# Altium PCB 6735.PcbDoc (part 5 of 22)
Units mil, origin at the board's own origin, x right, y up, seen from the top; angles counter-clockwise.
Board outline 2641.73 x 5165.35 mil, 6 copper layers (Top, Inner Layer 2, Inner Layer 3, Inner Layer 4, Inner Layer 5, Bottom), stack 35.7 mil thick; 1011 components, 790 nets, 4118 pads, 9325 vias.
Unrouted connection lines stored in the file: 4610.
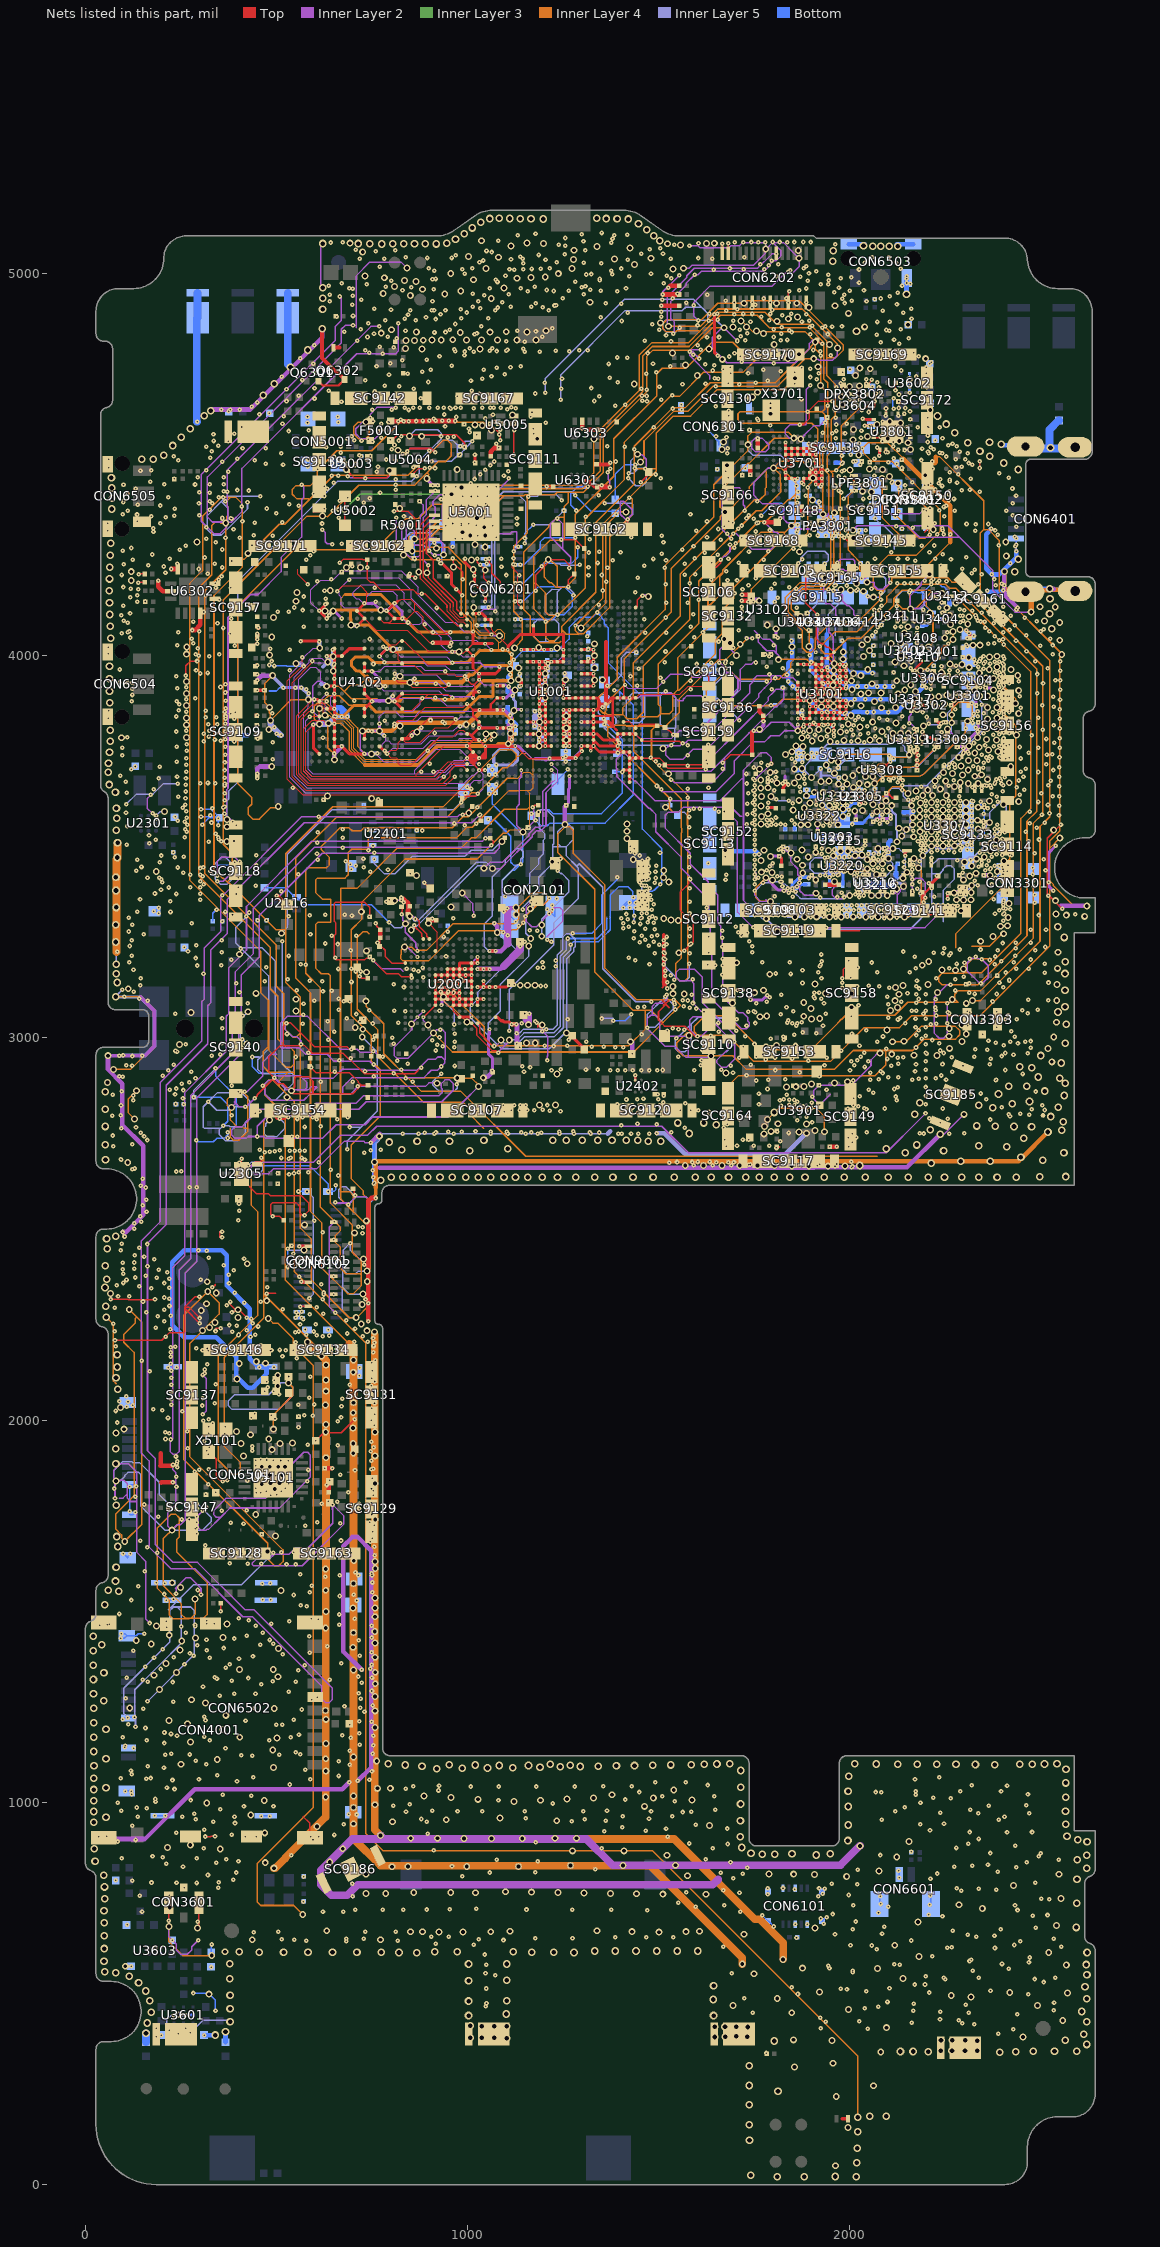
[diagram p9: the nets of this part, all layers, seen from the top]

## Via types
v1: diameter 12, hole 4, Top to Inner Layer 2, 3329 vias
v2: diameter 12, hole 4, Inner Layer 5 to Bottom, 3071 vias
v3: diameter 18, hole 10, Inner Layer 2 to Inner Layer 5, 1928 vias
v4: diameter 10, hole 4, Top to Inner Layer 2, 525 vias
v5: diameter 20, hole 12, Top to Bottom, 472 vias

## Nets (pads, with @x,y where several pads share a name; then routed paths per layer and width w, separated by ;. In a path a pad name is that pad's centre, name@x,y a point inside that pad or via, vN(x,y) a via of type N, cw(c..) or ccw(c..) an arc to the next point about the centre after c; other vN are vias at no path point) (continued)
CHD_DM: U1001.T4 U2001.M1 | length 749.7
  Top w4: v1(863.31,3311.09) 868.02,3311.09 872.95,3306.16 ; 872.95,3306.49 872.95,3306.16 ; U2001.M1@899.83,3258.94 892.94,3265.83 892.94,3272.17 872.95,3292.16 872.95,3306.16
  Inner Layer 2 w3: v4(1218.95,3716.51) 1235.45,3700.01 1235.45,3670.99 1228.95,3664.49
  Inner Layer 2 w4: v3(848.31,3318.09) 856.31,3318.09 v1(863.31,3311.09) ; v3(1064.99,3443.16) 1085.56,3443.16 1168.97,3526.56 1168.97,3530.96 1180.6,3542.59 1192.34,3542.59 1204.95,3555.21 1204.95,3642.03 1218.03,3655.11 1222.92,3660 1225.98,3663.05 1227.52,3663.05 1228.95,3664.49
  Inner Layer 5 w4: v3(848.31,3318.09) 859.31,3307.09 870.62,3307.09 1022.62,3459.09 1049.06,3459.09 v3(1064.99,3443.16)
CHD_DP: U1001.T3 U2001.N1 | length 697.7
  Top w4: v1(860.31,3295.09) 858.97,3293.74 880.31,3272.4 880.31,3265.21 885.34,3260.19 U2001.N1@884.09,3258.94
  Inner Layer 2 w3: v4(1218.95,3700.77) 1229.45,3690.26 1229.45,3675.99 1225.26,3671.8 1224.95,3671.8
  Inner Layer 2 w4: v3(852.41,3282.29) 851.19,3283.52 861.54,3293.87 v1(860.31,3295.09) ; v3(1042.86,3443.89) 1058.06,3459.09 1090.18,3459.09 1159.31,3528.22 1159.31,3532.62 1177.78,3551.09 1189.52,3551.09 1196.95,3558.52 1196.95,3645.35 1223.4,3671.8 1224.95,3671.8
  Inner Layer 5 w4: v3(852.41,3282.29) 857.16,3282.29 1024.95,3450.09 1042.86,3450.09 v3(1042.86,3443.89)
CHR_LDO: C2041.1 R2192.2 U2001.P3 U2116.1 | length 553.8
  Top w4: C2041.1@826.95,3343.49 828.31,3343.49 828.31,3337.49 v1(827.31,3323.09)
  Inner Layer 2 w4: v1(827.31,3323.09) 830.31,3323.09 830.31,3307.91 838.17,3300.05 v3(836.95,3298.83) 836.95,3276.54 864.45,3249.04 864.45,3238.53 868.34,3234.64 v4(868.34,3227.44)
  Inner Layer 5 w4: v2(794.22,3302.72) 808.85,3288.09 826.21,3288.09 v3(836.95,3298.83)
  Bottom w4: R2192.2@468.31,3393.09 523.14,3393.09 548.39,3367.83 U2116.1@551.93,3367.84 571.68,3348.09 748.85,3348.09 v2(794.22,3302.72)
CKE: U1001.D4 U4102.R2 U4102.T2 | length 665.2
  Top w3: v1(587.08,3840.61) 588,3841.52 U4102.T2@611.82,3841.53 U4102.R2@611.82,3861.21
  Inner Layer 2 w3: v1(587.08,3840.61) 576.58,3830.11 576.58,3700.36 592.33,3684.61 914.48,3684.61 924.46,3694.58 941.31,3694.58 966.46,3719.74 1026.75,3719.74 v4(1029.98,3716.51)
CLK0_C: U1001.E9 U4102.N3 | length 634.7
  Top w3: U1001.E9@1045.72,3795.25 v4(1045.73,3779.5)
  Inner Layer 2 w3: v3(612.08,3862.11) 620.08,3870.11 620.08,3889.16 v1(631.5,3900.58) ; v4(1045.73,3779.5) 1045.73,3792.75 v3(1048.08,3795.11)
  Inner Layer 4 w3: v3(612.08,3862.11) 628.22,3862.11 654.28,3836.05 678.01,3836.05 702.48,3811.58 702.48,3758.22 731.23,3729.47 865.08,3729.47 914.71,3779.11 1043.08,3779.11 1048.08,3784.11 v3(1048.08,3795.11)
CLK0_T: U1001.F9 U4102.P3 | length 622.5
  Top w3: v4(1061.47,3779.5) U1001.F9@1061.47,3795.25
  Inner Layer 2 w3: v3(627.08,3844.11) 627.08,3876.48 v1(631.5,3880.89) ; v4(1061.47,3779.5) 1061.47,3784.41 v3(1069.35,3792.29)
  Inner Layer 4 w3: v3(627.08,3844.11) 637.69,3844.11 651.77,3830.03 675.54,3830.03 696.48,3809.09 696.48,3755.64 728.7,3723.42 867.51,3723.42 917.2,3773.11 1046.08,3773.11 1057.84,3784.86 1061.93,3784.86 v3(1069.35,3792.29)
CLK_WCN: R5001.3 U3101.H1 | length 2463.2
  Top w4: R5001.3@849.08,4341.11 850.95,4341.11 v1(850.95,4335.49)
  Inner Layer 2 w4: v1(850.95,4335.49) 860.73,4325.71 v3(860.73,4305.07) ; v3(1893.37,4023.8) 1894.01,4024.44 1910.27,4008.19 v4(1910.9,4008.83)
  Inner Layer 4 w4: v3(860.73,4305.07) 886.37,4305.07 920.39,4339.09 1024.4,4339.09 1052.93,4367.63 1052.93,4405.09 1084.74,4436.9 1300.65,4436.9 1346.27,4482.52 1346.27,4579.66 1458.19,4691.57 1458.19,4784.27 1482.88,4808.97 1579.3,4808.97 1660.82,4890.49 1757.44,4890.49 1790.34,4857.59 1894.01,4857.59 1931.31,4820.29 1931.31,4724.87 1942.31,4713.87 1942.31,4543.8 1929.31,4530.8 1929.31,4489.62 1944.31,4474.62 1944.31,4361.92 1950.22,4356.01 1950.22,4197.9 1933.66,4181.33 1897.18,4181.33 1895.97,4182.55 1872.51,4182.55 1839.1,4149.15 1839.1,4120.46 1839.18,4120.38 1839.18,4113.63 1893.37,4059.43 v3(1893.37,4023.8)
CMMCLK: CON6201.20 R6212.2 U1001.Y27 | length 1079.4
  Top w3: v4(1281.94,4078.72) U1001.Y27@1281.94,4079.48 ; v4(1281.94,4078.72) U1001.Y27@1281.94,4079.48 ; v4(1281.94,4078.72) U1001.Y27@1281.94,4079.48 ; v4(1281.94,4078.72) U1001.Y27@1281.94,4079.48 ; U1001.Y27@1281.95,4078.49 1282.06,4078.6 v4(1281.94,4078.72) U1001.Y27@1281.95,4078.49
  Inner Layer 2 w4: v4(1281.94,4078.72) 1291.84,4078.71 1297.39,4073.16 v3(1296.31,4072.09)
  Inner Layer 4 w4: v3(1296.31,4072.09) 1360.95,4136.73 1360.95,4339.78 1397.49,4376.32 v3(1414.55,4376.32)
  Inner Layer 5 w4: v2(1055.45,4126.99) 1063.31,4134.85 1063.31,4399.09 1093.31,4429.09 1271.85,4429.09 v2(1281.47,4419.46) ; v2(1388.94,4369.7) 1395.56,4376.32 v3(1414.55,4376.32)
  Bottom w4: CON6201.20@1046.63,4127.16 1046.63,4126.99 v2(1055.45,4126.99) ; v2(1281.47,4419.46) 1323.37,4377.57 1388.94,4377.57 R6212.2@1388.94,4376.86 ; R6212.2@1386.31,4373.09 R6212.2@1388.94,4376.86 ; R6212.2@1388.94,4376.86 1389.43,4377.57 1389.14,4372.91 v2(1388.94,4369.7) R6212.2@1388.94,4376.86
CMMCLK_SUB: CON6202.12 R6212.1 | length 1746.8
  Inner Layer 2 w4: v3(1525.31,4862.09) 1521.95,4865.45 1521.95,4938.28 1544.99,4961.31 1573.31,4989.63 1573.31,4994.09 1592.71,5013.49 1758.61,5013.49 1796.17,5051.05 v1(1807.45,5051.05) ; v3(1905.31,4777.09) 1905.31,4776.09 1916.31,4776.09 1919.31,4773.09 1954.29,4773.09 1967.31,4786.12 v3(1967.31,4805.09)
  Inner Layer 4 w4: v3(1452.04,4506.42) 1461.31,4515.68 1461.31,4561.7 1538.7,4639.09 1575.97,4639.09 1641.97,4705.09 1810.47,4705.09 1882.47,4777.09 v3(1905.31,4777.09) ; v3(1525.31,4862.09) 1609.49,4862.09 1654.49,4907.09 1875.17,4907.09 1967.31,4814.94 v3(1967.31,4805.09)
  Inner Layer 5 w4: v2(1438.84,4499.29) 1444.92,4499.29 v3(1452.04,4506.42)
  Bottom w4: R6212.1@1386.31,4409.09 1386.31,4475.19 1410.41,4499.29 v2(1438.84,4499.29)
CONN_RSTB: U1001.B29 U5001.2 | length 408.4
  Top w3: 962.08,4128.11 962.08,4117.54 978.83,4100.79 989.06,4100.79 U1001.B29@998.48,4110.21
  Top w4: v1(896.95,4236.83) 897.36,4236.83 897.36,4203.45 962.08,4138.74 962.08,4128.11 ; U5001.2@913.02,4430.23 913.9,4431.11 v1(915.08,4431.11)
  Inner Layer 2 w4: v1(896.95,4236.83) 884.31,4249.47 884.31,4361.73 891.31,4368.73 891.31,4407.34 v1(915.08,4431.11)
CONN_SCLK: U1001.B27 U5001.6 | length 371.8
  Top w3: 945.95,4125.09 945.95,4116.15 973.61,4088.49 988.71,4088.49 990.95,4086.24 994.7,4082.49 U1001.B27@998.48,4078.72
  Top w4: U5001.6@913.02,4367.24 913.02,4368.35 902.06,4368.35 876.31,4342.6 876.31,4201.74 945.95,4132.11 945.95,4125.09
CONN_SDATA: U1001.B28 U5001.7 | length 337.7
  Top w3: 953.98,4126.09 953.98,4117.15 976.5,4094.64 990.48,4094.64 990.65,4094.47 U1001.B28@998.48,4094.47
  Top w4: U5001.7@913.02,4351.49 913.02,4352.6 902.06,4352.6 884.31,4334.85 884.31,4205.09 910.31,4179.09 910.42,4179.09 953.98,4135.52 953.98,4126.09
CONN_SEN: U1001.A29 U5001.8 | length 280.1
  Top w4: U5001.8@913.02,4335.74 913.02,4336.83 902.08,4336.83 892.31,4327.07 892.31,4267.09 909.95,4249.45 909.95,4202.83 971.31,4141.47 971.31,4121.63 U1001.A29@982.73,4110.21
CONN_XO_IN: R5001.2 U1001.E27 U5001.10 | length 591.6
  Top w4: v1(826.95,4340.91) R5001.2@829.08,4341.11 ; v1(912.31,4295.09) 912.31,4301.24 915.31,4304.24 U5001.10@913.02,4304.24 ; U1001.E27@1045.72,4078.72 1045.72,4071.68 v4(1062.31,4055.09)
  Inner Layer 2 w4: v1(826.95,4340.91) 826.95,4297.55 849.6,4274.89 v3(854.86,4273.56) ; v1(912.31,4295.09) 912.53,4295.3 924.48,4283.35 920.98,4282.85 v3(918.36,4281.22) ; v4(1062.31,4055.09) 1065.31,4052.09 v3(1083.31,4052.09)
  Inner Layer 4 w4: v3(854.86,4273.56) 884.04,4273.56 894.05,4283.57 920.98,4283.57 v3@920.98,4282.85 ; v3(918.36,4281.22) v3@920.98,4282.85 ; v3(1083.31,4052.09) 1081.61,4053.79 1070.95,4053.79 1070.65,4053.49 1030.91,4053.49 1016.31,4068.09 1016.31,4092.17 995.31,4113.17 995.31,4237.19 990.95,4241.55 973.02,4259.49 948.93,4283.57 924.7,4283.57 v3@920.98,4282.85
CS0_N: U1001.B4 U4102.U3 | length 637
  Top w3: U4102.U3@631.5,3821.84 621.68,3831.65 593.78,3831.65 570.58,3808.46 570.58,3697.36 589.33,3678.61 916.33,3678.61 954.24,3716.51 U1001.B4@998.48,3716.51
CS1_N: U1001.B3 U4102.T3 | length 733.8
  Top w3: U4102.T3@631.5,3841.53 621.65,3851.37 621.65,3865.25 615.88,3871.02 592.75,3871.02 558.58,3836.86 558.58,3691.36 583.33,3666.61 936.11,3666.61 954.18,3684.68 954.18,3699.61 964.81,3710.24 989,3710.24 U1001.B3@998.48,3700.77
CS_N: R2139.1 U2001.E15 | length 687
  Top w4: U2001.E15@1009.95,3038.83 U2001.E15@1010.07,3038.71 ; v1(1080.05,2960.81) 1074.03,2966.83 1063.98,2966.83 1023.31,3007.5 1023.31,3025.23 U2001.E15@1010.07,3038.47 ; U2001.E15@1010.07,3038.47 U2001.E15@1010.07,3038.71 ; U2001.E15@1010.07,3038.47 U2001.E15@1010.07,3038.71
  Inner Layer 2 w4: v1(1080.05,2960.81) 1080.05,2962.93 1109.43,2992.31 1109.43,2994.83 v3(1108.95,2994.83)
  Inner Layer 5 w4: v3(1108.95,2994.83) 1129.07,2994.83 1147.33,3013.09 1225.31,3013.09 1242.31,3030.09 1242.31,3213.79 1257.31,3228.79 1257.31,3252.4 1263.66,3258.75 v2(1262.31,3260.09)
  Bottom w4: v2(1262.31,3260.09) 1339,3260.09 1363.31,3284.4 R2139.1@1363.31,3313.09
CS_P: R2138.1 U2001.D15 | length 669.4
  Top w4: U2001.D15@1025.82,3038.47 1031.31,3032.97 1031.31,3013.74 1065.9,2979.15 1068.95,2979.15 v1(1068.95,2978.83)
  Inner Layer 2 w4: v1(1068.95,2978.83) 1075.23,2980.24 1086.95,2991.96 v3(1086.95,2994.83)
  Inner Layer 5 w4: v3(1086.95,2994.83) 1101.95,2979.83 1125.56,2979.83 1149.19,3003.46 1227,3003.46 1250.31,3026.78 1250.31,3210.37 1269.31,3229.37 v2(1269.31,3243.83)
  Bottom w4: v2(1269.31,3243.83) 1277.57,3252.09 1342.32,3252.09 1361.75,3271.52 1369.08,3278.86 1373.31,3283.09 R2138.1@1373.31,3313.09
D_GND: ANT3607.1 ANT3607.2 ANT3608.1 ANT3608.2 ANT3609.1 ANT3609.2 ANT3610.1 ANT3610.2 ANT5001.1 ANT5001.2 ANT5002.1 ANT5002.2 ANT5004.1 ANT5004.2 C1102.2 C1103.2 C1104.2 C1105.2 C1106.2 C2007.2 C2008.2 C2011.2 C2012.2 C2013.2 C2014.2 C2015.2 C2016.2 C2017.2 C2018.2 C2019.2 C2020.2 C2022.2 C2023.1 C2027.2 C2030.2 C2031.2 C2032.2 C2033.2 C2034.2 C2036.2 C2039.2 C2040.2 C2041.2 C2042.2 C2043.2 C2044.2 C2046.2 C2047.2 C2048.2 C2051.2 C2054.2 C2055.2 C2056.2 C2057.2 C2058.2 C2101.1 C2312.2 C2315.2 C2319.2 C2320.2 C2322.2 C2323.2 C2402.2 C2403.2 C2411.2 C2412.2 C3101.2 C3102.2 C3103.2 C3104.2 C3105.2 C3106.2 C3108.1 C3109.2 C3110.2 C3112.2 C3116.2 C3205.2 C3210.2 C3211.2 C3215.2 C3216.2 C3222.2 C3223.2 C3226.1 C3228.1 C3233.2 C3239.2 C3241.2 C3242.2 C3243.2 C3244.2 C3245.2 C3248.2 C3249.2 C3250.1 C3251.1 C3254.1 C3255.2 C3257.2 C3258.2 C3259.2 C3260.2 C3263.2 C3264.2 C3265.2 C3271.2 C3272.2 C3273.2 C3289.2 C3290.2 C3291.2 C3304.2 C3312.2 C3313.2 C3324.2 C3339.2 C3340.1 C3348.2 C3362.2 C3383.2 C3407.2 C3435.2 C3438.1 C3439.1 C3447.1 C3456.1 C3457.1 C3601.1 C3602.1 C3603.2 C3604.2 C3702.2 C3703.2 C3704.2 C3705.2 C3706.2 C3707.2 C3709.2 C3710.2 C3802.2 C3805.2 C3806.2 C3901.2 C3902.2 C3903.2 C3905.2 C3906.2 C3908.2 C3909.2 C3910.2 C3911.2 C3912.2 C3913.2 C3914.2 C3915.2 C3916.2 C4001.2 C4101.2 C4102.2 C4103.2 C4104.2 C4105.2 C4106.2 C4107.2 C4108.2 C4109.2 C4110.2 C4111.2 C4112.2 C4113.2 C4114.2 C4115.2 C4116.2 C5001.2 C5002.1 C5003.2 C5005.1 C5006.1 C5007.1 C5008.1 C5009.1 C5011.2 C5012.1 C5013.2 C5014.2 C5015.1 C5017.2 C5104.2 C5105.1 C5106.2 C5107.1 C5111.2 C5112.1 C5115.1 C5116.1 C5117.1 C5119.1 C5120.1 C5121.1 C5122.2 C5123.2 C5124.2 C5125.2 C5126.2 C6007.2 C6008.2 C6012.2 C6015.2 C6016.2 C6019.2 C6021.1 C6023.1 C6024.2 C6031.2 C6032.2 C6035.2 C6038.2 C6039.2 C6101.2 C6106.2 C6107.2 C6201.2 C6202.2 C6203.2 C6204.1 C6205.2 C6206.2 C6207.2 C6210.2 C6303.2 C6304.2 C6305.2 C6306.2 C6308.2 C6310.2 C6313.2 C6314.2 C6315.2 C6501.2 C6502.2 C6503.2 C6601.2 C9001.2 C10004.2 C10005.2 C10006.2 C10007.2 C10008.2 C10009.2 C10010.2 C10012.2 C10016.2 C10017.2 C10018.2 C10025.2 C10027.2 C10035.2 C10036.2 C10037.2 C10038.2 C10039.2 C10040.2 C10046.2 C10047.2 C10052.2 C10053.2 C10059.2 C10060.2 C10062.2 C10064.2 C10065.2 C10066.2 C10067.2 C10068.2 C10069.2 C10070.2 C10071.2 C10072.2 C10073.2 C10075.2 C10076.2 C10077.2 C10078.2 C10079.2 C10080.2 C10082.2 C10083.2 C10084.2 C10085.2 C10086.2 C10087.2 C10088.2 C10089.2 C10090.2 C10091.2 C10092.2 C10093.2 C10094.2 C10095.2 C10096.2 C10097.2 C10098.2 C10099.2 C10100.2 CON2101.4 CON2101.5 CON3301.3 CON3301.4 CON3301.5 CON3301.6 CON3303.1 CON3303.3 CON3303.4 CON3601.1 CON3601.3 CON3601.4 CON3802.3 CON3802.4 CON3802.5 CON3802.6 CON4001.6 CON4001.11 CON4001.13 CON4001.14 CON4001.15 CON4001.16 CON4001.17 CON4001.18 CON4001.19 CON5001.3 CON5001.4 CON5001.5 CON5001.6 CON6101.1 CON6101.5 CON6101.6 CON6101.10 CON6101.11 CON6101.12 CON6101.13 CON6101.14 CON6102.5 CON6102.7 CON6102.11 CON6102.15 CON6102.18 CON6102.21 CON6102.24 CON6102.27 CON6102.30 CON6201.1 CON6201.4 CON6201.7 CON6201.10 CON6201.13 CON6201.17 CON6201.27 CON6201.28 CON6201.30 CON6202.1 CON6202.7 CON6202.13 CON6202.19 CON6202.25 CON6202.28 CON6202.30 CON6301.4 CON6301.7 CON6301.8 CON6401.5 CON6401.6 CON6401.7 CON6401.8 CON6401.9 CON6501.5 CON6501.9 CON6501.11 CON6501.12 CON6501.13 CON6501.14 CON6501.15 CON6501.16 CON6501.17 CON6501.18 CON6502.5 CON6502.9 CON6502.11 CON6502.12 CON6502.13 CON6502.14 CON6502.15 CON6502.16 CON6502.17 CON6502.18 CON6503.1 CON6503.4 CON6503.5 CON6504.4 CON6504.5 CON6505.1 CON6505.4 CON6505.5 CON6601.2 CON6601.3 CON6601.4 CON9001.38 CON9001.40 CON9001.41 CON9001.42 CON9001.43 CON9001.44 D2103.A DIPX3801.2 DIPX3801.4 DIPX3801.6 DPX3802.2 DPX3802.4 DPX3802.5 DPX3802.7 DPX3802.9 F5001.1 F5001.3 F5001.5 F5001.7 L3214.2 L3218.1 L3219.1 L3221.1 L3222.1 L3223.2 L3234.2 L3301.2 L3302.2 L3303.2 L3304.2 L3311.2 L3313.2 L3314.2 L3315.2 L3317.2 L3318.2 L3322.2 L3330.2 L3331.2 L3332.1 L3338.2 L3340.1 L3342.2 L3344.1 L3346.2 L3347.2 L3350.2 L3351.2 L3402.1 L3411.1 L3414.1 L3415.2 L3418.2 L3421.2 L3429.1 L3430.1 L3431.1 L3433.2 L3437.1 L3441.1 L3442.1 L3499.2 L3601.2 L3602.2 L3603.2 L3605.2 L3607.2 L3610.1 L3612.1 L3801.2 L3802.2 L3803.2 L3804.2 L3805.2 L3806.2 L3815.2 L3816.2 L3821.2 L3822.2 L3901.2 L5004.2 L5005.2 L5006.2 L5007.2 L5008.2 L5009.2 L5010.2 L5011.2 L5012.2 L6002.1 LED2302.2 LPF3801.1 LPF3801.2 LPF3801.3 LPF3801.5 NTC3701.2 NTC6301.2 NTC6302.2 PA3901.7 PA3901.11 Q6301.2 Q6302.2 R1101.2 R1106.2 R1201.2 R1227.2 R2003.1 R2030.2 R2033.2 R2137.2 R2138.2 R2310.2 R2406.1 R2407.1 R2417.1 R3102.2 R3103.2 R3105.2 R3107.2 R3108.2 R3201.2 R3226.2 R3231.2 R3302.2 R3306.2 R3327.2 R3328.2 R3601.2 R3605.2 R3607.2 R3614.2 R3622.2 R3624.2 R3627.2 R3628.2 R3631.2 R3701.1 R3703.1 R3704.2 R3718.1 R3719.1 R3732.2 R3818.2 R3819.2 R3903.2 R3910.2 R4103.1 R4104.1 R5006.2 R5013.2 R5128.2 R5129.2 R6006.2 R6007.2 R6012.1 R6029.2 R6510.1 SC9101.1 SC9101.2 SC9101.3 SC9101.4 SC9101.5 SC9102.1 SC9102.2 SC9102.3 SC9102.4 SC9102.5 SC9103.1 SC9103.2 SC9103.3 SC9103.4 SC9103.5 SC9104.1 SC9104.2 SC9104.3 SC9104.4 SC9104.5 SC9105.1 SC9105.2 SC9105.3 SC9105.4 SC9105.5 SC9106.1 SC9106.2 SC9106.3 SC9106.4 SC9106.5 SC9107.1 SC9107.2 SC9107.3 SC9107.4 SC9107.5 SC9108.1 SC9108.2 SC9108.3 SC9108.4 SC9108.5 SC9109.1 SC9109.2 SC9109.3 SC9109.4 SC9109.5 SC9110.1 SC9110.2 SC9110.3 SC9110.4 SC9110.5 SC9111.1 SC9111.2 SC9111.3 SC9111.4 SC9111.5 SC9112.1 SC9112.2 SC9112.3 SC9112.4 SC9112.5 SC9113.1 SC9113.2 SC9113.3 SC9113.4 SC9113.5 SC9114.1 SC9114.2 SC9114.3 SC9114.4 SC9114.5 SC9115.1 SC9115.2 SC9115.3 SC9115.4 SC9115.5 SC9116.1 SC9116.2 SC9116.3 SC9116.4 SC9116.5 SC9117.1 SC9117.2 SC9117.3 SC9117.4 SC9117.5 SC9118.1 SC9118.2 SC9118.3 SC9118.4 SC9118.5 SC9119.1 SC9119.2 SC9119.3 SC9119.4 SC9119.5 SC9120.1 SC9120.2 SC9120.3 SC9120.4 SC9120.5 SC9121.1 SC9121.2 SC9121.3 SC9121.4 SC9121.5 SC9128.1 SC9128.2 SC9128.3 SC9129.1 SC9129.2 SC9129.3 SC9130.1 SC9130.2 SC9130.3 SC9131.1 SC9131.2 SC9131.3 SC9132.1 SC9132.2 SC9132.3 SC9133.1 SC9133.2 SC9133.3 SC9134.1 SC9134.2 SC9134.3 SC9135.1 SC9135.2 SC9135.3 SC9136.1 SC9136.2 SC9136.3 SC9137.1 SC9137.2 SC9137.3 SC9138.1 SC9138.2 SC9138.3 SC9138.4 SC9138.5 SC9139.1 SC9139.2 SC9139.3 SC9139.4 SC9139.5 SC9140.1 SC9140.2 SC9140.3 SC9140.4 SC9140.5 SC9141.1 SC9141.2 SC9141.3 SC9141.4 SC9141.5 SC9142.1 SC9142.2 SC9142.3 SC9142.4 SC9142.5 SC9145.1 SC9145.2 SC9145.3 SC9146.1 SC9146.2 SC9146.3 SC9147.1 SC9147.2 SC9147.3 SC9148.1 SC9148.2 SC9148.3 SC9149.1 SC9149.2 SC9149.3 SC9150.1 SC9150.2 SC9150.3 SC9151.1 SC9151.2 SC9151.3 SC9152.1 SC9152.2 SC9152.3 SC9153.1 SC9153.2 SC9153.3 SC9153.4 SC9153.5 SC9154.1 SC9154.2 SC9154.3 SC9154.4 SC9154.5 SC9155.1 SC9155.2 SC9155.3 SC9155.4 SC9155.5 SC9156.1 SC9156.2 SC9156.3 SC9156.4 SC9156.5 SC9157.1 SC9157.2 SC9157.3 SC9157.4 SC9157.5 SC9158.1 SC9158.2 SC9158.3 SC9158.4 SC9158.5 SC9159.1 SC9159.2 SC9159.3 SC9159.4 SC9159.5 SC9161.1 SC9161.2 SC9161.3 SC9162.1 SC9162.2 SC9162.3 SC9163.1 SC9163.2 SC9163.3 SC9164.1 SC9164.2 SC9164.3 SC9165.1 SC9165.2 SC9165.3 SC9166.1 SC9166.2 SC9166.3 SC9167.1 SC9167.2 SC9167.3 SC9168.1 SC9168.2 SC9168.3 SC9169.1 SC9169.2 SC9169.3 SC9170.1 SC9170.2 SC9170.3 SC9171.1 SC9171.2 SC9171.3 SC9172.1 SC9172.2 SC9172.3 SC9185.1 SC9185.2 SC9185.3 SC9186.1 SC9186.2 SC9186.3 SH1002.2 SH1003.1 SH1005.1 SH6003.2 SH6004.2 TP2029.1 U1001.A27 U1001.AA7 U1001.AA9 U1001.AA11 U1001.AA13 U1001.AA15 U1001.AA17 U1001.AA19 U1001.AA21 U1001.AA23 U1001.AB7 U1001.AB9 U1001.AB11 U1001.AB13 U1001.AB15 U1001.AB17 U1001.AB19 U1001.AB21 U1001.AB23 U1001.AC7 U1001.AC8 U1001.AC9 U1001.AC10 U1001.AC11 U1001.AC12 U1001.AC13 U1001.AC15 U1001.AC17 U1001.AC18 U1001.AC19 U1001.AC21 U1001.AC22 U1001.AC23 U1001.AE11 U1001.AE14 U1001.AG6 U1001.AG7 U1001.AG8 U1001.AG9 U1001.AG15 U1001.AH3 U1001.AH6 U1001.AH9 U1001.AH11 U1001.AH15 U1001.AJ1 U1001.AJ2 U1001.AJ3 U1001.AJ4 U1001.AJ5 U1001.AJ6 U1001.AJ9 U1001.AJ15 U1001.AK5 U1001.AK9 U1001.AK10 U1001.AK15 U1001.AK30 U1001.AL5 U1001.AL8 U1001.B5 U1001.B7 U1001.B9 U1001.B14 U1001.B18 U1001.B23 U1001.C6 U1001.C15 U1001.C22 U1001.C26 U1001.C29 U1001.D3 U1001.D5 U1001.D8 U1001.D10 U1001.D11 U1001.D18 U1001.D29 U1001.E3 U1001.E24 U1001.E28 U1001.E31 U1001.F27 U1001.F28 U1001.G10 U1001.G13 U1001.G15 U1001.G17 U1001.H10 U1001.H13 U1001.H15 U1001.H17 U1001.K7 U1001.K9 U1001.L3 U1001.L13 U1001.L17 U1001.L18 U1001.L23 U1001.L30 U1001.M7 U1001.M9 U1001.M11 U1001.M21 U1001.M23 U1001.N7 U1001.N9 U1001.N11 U1001.N21 U1001.N23 U1001.N27 U1001.P7 U1001.P8 U1001.P9 U1001.P10 U1001.P11 U1001.P12 U1001.P13 U1001.P14 U1001.P15 U1001.P16 U1001.P17 U1001.P18 U1001.P19 U1001.P20 U1001.P21 U1001.R7 U1001.R8 U1001.R9 U1001.R10 U1001.R11 U1001.R12 U1001.R13 U1001.R14 U1001.R15 U1001.R16 U1001.R17 U1001.R18 U1001.R19 U1001.R20 U1001.R21 U1001.T7 U1001.T9 U1001.T11 U1001.T21 U1001.T23 U1001.U21 U1001.V7 U1001.V8 U1001.V9 U1001.V10 U1001.V11 U1001.V12 U1001.V13 U1001.V15 U1001.V16 U1001.V17 U1001.V18 U1001.V21 U1001.V22 U1001.V23 U1001.W2 U1001.W7 U1001.W8 U1001.W9 U1001.W10 U1001.W11 U1001.W12 U1001.W13 U1001.W15 U1001.Y13 U1001.Y15 U2001.A3 U2001.A9 U2001.A14 U2001.B3 U2001.B6 U2001.B9 U2001.B16 U2001.C6 U2001.C8 U2001.C9 U2001.C11 U2001.D4 U2001.D5 U2001.D6 U2001.D9 U2001.D11 U2001.D12 U2001.E5 U2001.E6 U2001.E7 U2001.E8 U2001.E9 U2001.E10 U2001.E11 U2001.E12 U2001.E14 U2001.F11 U2001.F12 U2001.G6 U2001.G7 U2001.G8 U2001.G9 U2001.G10 U2001.G11 U2001.G12 U2001.G14 U2001.H6 U2001.H7 U2001.H8 U2001.H9 U2001.H10 U2001.H11 U2001.H12 U2001.J6 U2001.J7 U2001.J8 U2001.J9 U2001.J10 U2001.J11 U2001.K7 U2001.K8 U2001.K9 U2001.K10 U2001.K11 U2001.K12 U2001.L3 U2001.L7 U2001.L8 U2001.L9 U2001.L10 U2001.L11 U2001.L12 U2001.N13 U2001.N14 U2001.P4 U2001.P14 U2001.R7 U2001.T5 U2301.A3 U2305.3 U2305.7 U2401.1 U2401.3 U2402.C2 U3101.C3 U3101.C4 U3101.C5 U3101.C6 U3101.C7 U3101.C9 U3101.C10 U3101.C11 U3101.C12 U3101.D3 U3101.D4 U3101.D5 U3101.D6 U3101.D7 U3101.D8 U3101.D9 U3101.D10 U3101.D11 U3101.D12 U3101.E1 U3101.E3 U3101.E4 U3101.E5 U3101.E6 U3101.E7 U3101.E8 U3101.E9 U3101.E10 U3101.E11 U3101.E12 U3101.E13 U3101.E14 U3101.E15 U3101.F2 U3101.F4 U3101.F5 U3101.F6 U3101.F7 U3101.F8 U3101.F9 U3101.F10 U3101.F11 U3101.F12 U3101.F13 U3101.G2 U3101.G3 U3101.G4 U3101.G5 U3101.G6 U3101.G7 U3101.G8 U3101.G9 U3101.G10 U3101.G11 U3101.G12 U3101.G13 U3101.H3 U3101.H4 U3101.H5 U3101.H6 U3101.H7 U3101.H8 U3101.H9 U3101.H10 U3101.H11 U3101.H13 U3101.J3 U3101.J4 U3101.J8 U3101.J9 U3101.J10 U3101.J11 U3101.J12 U3101.J13 U3101.K3 U3101.K7 U3101.K8 U3101.K9 U3101.K12 U3101.K13 U3101.L3 U3101.L6 U3101.L7 U3101.L8 U3101.L9 U3101.L10 U3101.L11 U3101.L12 U3101.L13 U3101.L14 U3102.3 U3203.1 U3203.2 U3203.14 U3203.15 U3203.20 U3203.22 U3203.24 U3203.27 U3203.31 U3203.34 U3203.36 U3203.38 U3203.40 U3203.43 U3203.44 U3203.45 U3203.46 U3203.47 U3203.48 U3203.49 U3203.50 U3210.1 U3210.3 U3210.4 U3210.6 U3215.2 U3215.3 U3215.5 U3216.2 U3220.3 U3301.2 U3301.4 U3301.5 U3301.7 U3301.8 U3302.5 U3302.6 U3302.9 U3305.2 U3305.3 U3305.5 U3305.7 U3305.8 U3305.10 U3306.2 U3306.4 U3306.5 U3306.7 U3307.1 U3307.4 U3307.11 U3307.12 U3307.13 U3307.14 U3307.15 U3307.16 U3307.18 U3307.20 U3307.21 U3307.23 U3307.38 U3307.39 U3308.2 U3308.4 U3308.5 U3308.7 U3309.2 U3309.4 U3309.5 U3309.7 U3309.8 U3313.2 U3313.4 U3313.5 U3313.7 U3317.1 U3322.2 U3322.5 U3323.1 U3401.6 U3401.9 U3402.15 U3403.2 U3403.5 U3404.2 U3404.3 U3404.5 U3406.2 U3406.5 U3407.2 U3407.5 U3408.2 U3408.5 U3410.1 U3411.2 U3411.3 U3411.5 U3412.2 U3412.3 U3412.5 U3414.2 U3414.5 U3601.2 U3601.6 U3601.9 U3602.2 U3602.6 U3602.9 U3603.3 U3604.3 U3701.B6 U3701.B7 U3701.B8 U3701.B9 U3701.C2 U3701.C3 U3701.C4 U3701.C5 U3701.C6 U3701.C7 U3701.C8 U3701.C9 U3701.D3 U3701.D4 U3701.D7 U3701.D8 U3701.E3 U3701.E4 U3701.E8 U3701.E9 U3701.F3 U3701.F4 U3701.F8 U3701.G3 U3701.G4 U3701.G5 U3701.G8 U3701.H2 U3701.H3 U3701.H4 U3701.H5 U3701.H6 U3701.H7 U3701.H8 U3801.1 U3801.2 U3801.4 U3801.6 U3801.7 U3801.9 U3801.11 U3801.12 U3801.14 U3801.15 U3801.17 U3801.20 U3801.21 U3901.A2 U3901.A3 U3901.C1 U4102.A3 U4102.A8 U4102.A12 U4102.AA2 U4102.AA4 U4102.AA8 U4102.AA11 U4102.B2 U4102.B7 U4102.B11 U4102.C3 U4102.C5 U4102.C8 U4102.C10 U4102.C12 U4102.C13 U4102.D7 U4102.F2 U4102.F13 U4102.G4 U4102.G8 U4102.G11 U4102.H3 U4102.H4 U4102.H5 U4102.H10 U4102.J4 U4102.J8 U4102.J13 U4102.K4 U4102.K8 U4102.K9 U4102.L4 U4102.L10 U4102.L12 U4102.M3 U4102.M4 U4102.M8 U4102.N4 U4102.N8 U4102.N13 U4102.P2 U4102.P4 U4102.P9 U4102.P12 U4102.R3 U4102.R4 U4102.R8 U4102.R13 U4102.T4 U4102.T8 U4102.U4 U4102.U10 U4102.U12 U4102.V4 U4102.V8 U4102.V9 U4102.W4 U4102.W8 U4102.W13 U4102.Y4 U4102.Y5 U4102.Y10 U5001.1 U5001.41 U5002.1 U5002.2 U5003.2 U5003.3 U5003.5 U5004.1 U5004.4 U5005.2 U5005.3 U5005.5 U5101.24 U5101.33 U6301.B1 U6302.4 U6302.6 U6302.8 U6302.13 U6302.15 U6303.6 U6303.9 VR2101.2 VR2102.2 X3701.2 X3701.4 X5101.2 X5101.3 X5101.4 | length 248885.6
  Top w3: 555.95,4226.49 555.95,4212.86 v1(581.99,4186.83) ; v1(566.95,3995.49) 566.95,3972.68 528.58,3934.31 528.58,3676.49 546.48,3658.3 567.95,3636.49 976.95,3636.49 979.25,3634.19 ; v1(593.83,3854.86) 585.58,3854.86 564.58,3833.86 564.58,3694.36 586.33,3672.61 927.12,3672.61 v1(937.75,3683.23) ; v1(593.83,3986.11) 593.83,3982.59 540.58,3929.34 540.58,3683.9 575.87,3648.61 1006.5,3648.61 v1@1007.77,3649.87 ; v1(596.08,3819.11) 576.58,3799.61 576.58,3700.23 592.2,3684.61 864.95,3684.61 ; v1(598.95,3885.49) 595.58,3885.49 552.58,3842.49 552.58,3688.87 580.84,3660.61 942.76,3660.61 v1(965.74,3683.59) ; U4102.P2@611.82,3880.9 616.08,3880.89 630.87,3866.11 630.87,3861.84 U4102.R3@631.5,3861.21 ; v1(658.33,4168.36) 672.58,4182.61 719.83,4182.61 736.06,4166.38 736.06,4142.93 v1(729.92,4136.8) ; 793.33,4085.86 794.08,4085.11 850.33,4085.11 901.33,4034.11 v1(909.04,4034.11) ; v1(808.66,3821.84) 818.51,3831.68 850.27,3831.68 850.34,3831.61 856.33,3831.61 889.33,3864.61 977.83,3864.61 ; v1(808.66,3939.95) 818.82,3930.11 841.83,3930.11 854.83,3917.11 943.33,3917.11 v1(950.83,3924.61) ; 816.01,4141.91 820.72,4146.61 824.28,4146.61 ; U4102.R13@828.35,3861.21 832.45,3857.11 855.08,3857.11 897.08,3899.11 ; U4102.N13@828.35,3900.58 829.82,3899.11 897.08,3899.11 ; v1(828.35,4097.43) 843.15,4097.43 861.58,4115.86 861.58,4116.61 ; 837.58,3782.65 837.58,3785.86 856.33,3804.61 865.33,3804.61 897.55,3836.82 898.89,3838.16 963.77,3838.16 968.6,3833.34 v1(968.71,3833.45) ; C2030.2@896.95,3308.49 896.95,3308.09 896.95,3300.76 920.81,3276.9 920.81,3232.68 U2001.L3@915.58,3227.44 ; v1(959.83,3981.61) 956.08,3977.86 956.08,3977.11 895.33,3977.11 834.06,4038.37 ; v1(959.95,3890.49) 958.2,3888.74 947.83,3899.11 897.08,3899.11 ; 979.25,3634.15 C10098.2@986.31,3627.09 ; U1001.B5@998.43,3732.26 989,3722.83 949.13,3722.83 910.91,3684.61 864.95,3684.61 ; U1001.B9@998.48,3795.25 988.96,3804.77 977.99,3804.77 961.33,3788.11 927.58,3788.11 852.58,3713.11 824.08,3713.11 818.51,3718.68 818.51,3727.45 812.7,3733.26 798.82,3733.26 v1(788.98,3743.1) 798.82,3752.94 812.7,3752.94 818.51,3758.75 818.51,3772.63 ; v4(998.48,3936.99) 988.75,3946.71 970.73,3946.71 964.33,3953.11 883.33,3953.11 860.83,3975.61 U4102.J13@832.06,3975.61 ; U1001.B23@998.48,4015.73 988.59,4005.84 977.6,4005.84 971.83,4011.61 896.83,4011.61 841.33,4067.11 760.25,4067.11 ; v4(1029.98,3779.51) 1041.37,3768.11 1041.37,3767.82 v4(1046.08,3763.11) ; U1001.F27@1061.47,4078.72 1061.47,4069.06 1067.26,4063.27 1067.37,4063.27 1067.77,4062.87 1067.96,4062.87 1104.95,4025.89 1104.95,4023.07 ; v1(1118.86,4239.68) 1116.95,4239.49 1116.95,4229.49 1130.95,4215.49 1130.95,4163.09 1130.79,4162.93 1130.79,4135.38 U1001.L30@1140.21,4125.96 ; SC9159.2@1628.26,3866.05 1619.3,3857.09 SC9159.2@1630.31,3865.45 ; SC9159.1@1630.31,3920.57 1576.79,3920.57 1555.31,3899.09 1510.31,3899.09 1510.24,3899.16 1448.84,3899.16 ; 760.25,4067.11 U4102.C8@729.93,4097.43 760.25,4067.11 ; v1(788.98,4018.69) U4102.G11@789.24,4018.95 ; v1(788.98,4018.69) 798.82,4028.53 813.61,4028.53 824.01,4038.93 827.79,4038.93 U4102.F13@828.35,4038.38 ; v1(788.98,4018.69) U4102.G11@789.24,4018.95 ; U4102.G11@789.24,4018.95 799.34,4008.85 812.7,4008.85 818.51,4003.04 818.51,3989.16 ; 818.51,3772.63 U4102.W13@828.35,3782.47 ; 818.51,3772.63 U4102.W13@828.35,3782.47 ; 818.51,3989.16 U4102.J13@828.35,3979.32 U4102.J13@832.06,3975.61 ; 818.51,3989.16 U4102.J13@832.06,3975.61 ; 818.57,4140.91 817.01,4139.34 817.01,4138.33 815.48,4136.8 810.9,4136.8 v1(808.66,4136.8) 813.48,4141.62 814.19,4140.91 815.01,4140.91 818.57,4140.91 ; 818.57,4140.91 824.28,4146.61 ; 824.28,4146.61 825.76,4148.09 850.63,4148.09 868.31,4130.41 ; U4102.W13@828.35,3782.47 U4102.W13@828.96,3780.98 ; U4102.W13@828.35,3782.47 828.35,3781.59 U4102.W13@828.96,3780.98 ; U4102.W13@828.35,3782.47 U4102.W13@828.96,3780.98 ; U4102.F13@828.35,4038.38 834.06,4038.37 ; U4102.F13@828.35,4038.38 834.06,4038.37 ; U4102.W13@828.96,3780.98 836.83,3773.11 876.58,3773.11 915.58,3812.11 949.33,3812.11 v1@968.83,3831.61 ; 861.58,4116.61 868.33,4116.61 884.08,4100.86 884.08,4078.36 905.83,4056.61 950.08,4056.61 v1(954.58,4061.11) 937.61,4061.11 868.31,4130.4 ; 861.58,4116.61 861.58,4137.13 868.31,4130.4 ; 864.95,3684.61 864.95,3689.99 938.71,3763.75 ; 938.71,3763.75 v4(998.48,3763.76) 998.13,3764.11 v4(998.48,3763.76) 938.71,3763.75 ; v1(968.71,3833.45) v1@968.83,3831.61 ; v1(968.71,3833.45) 968.83,3833.11 v1@968.83,3831.61 ; 977.87,3864.57 989.06,3864.57 ; 977.83,3864.61 977.87,3864.57 ; 989.06,3864.57 v4(998.48,3873.99) 989.06,3864.57 ; U1001.L30@1140.21,4125.96 1130.95,4135.22 U1001.L30@1140.21,4125.96 ; 1448.84,3899.16 1439.42,3889.74 1448.84,3899.16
